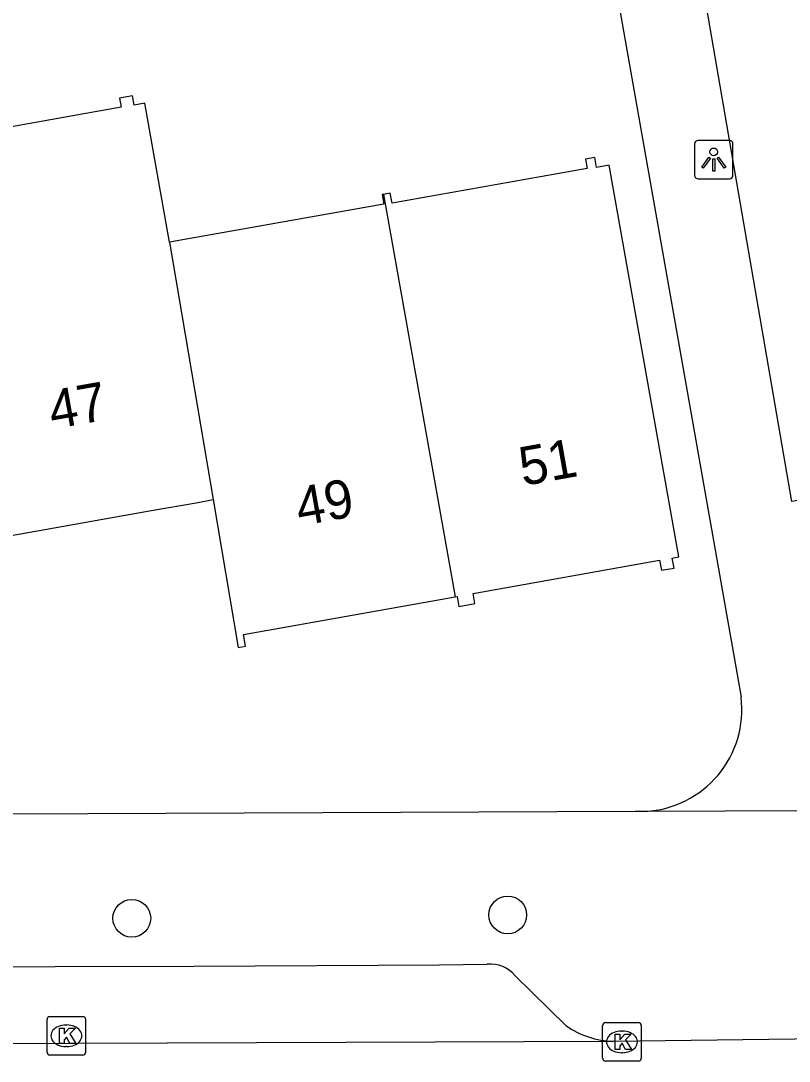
# Model space of a CAD drawing. Extents: x 157793 to 159380, y 380882 to 382313.
# Drawn here: x 158432.1 to 158452.01, y 381265.26 to 381292.23 of the extents above; entities that cross this region are included whole.
import ezdxf

# ---------------------------------------------------------------- set-up
doc = ezdxf.new("R2010")
doc.units = 0
for name, color, linetype in [('IMGEO_Boom', 7, 'Continuous'), ('IMGEO_Kolk', 7, 'Continuous'), ('IMGEO_Lichtpunt', 7, 'Continuous'), ('IMGEO_Pand', 7, 'Continuous'), ('IMGEO_Pand_nummerreeks', 7, 'Continuous'), ('IMGEO_Rijbaan_lokaal_gesloten', 7, 'Continuous'), ('IMGEO_Voetpad_open', 7, 'Continuous')]:
    doc.layers.add(name, color=color, linetype=linetype)

msp = doc.modelspace()

# ---------------------------------------------------------------- linework, layer by layer
at = {"layer": 'IMGEO_Boom'}
for centre in [(158434.973, 381268.967), (158444.714, 381269.054)]:
    msp.add_circle(centre, 0.489, dxfattribs=at)
at = {"layer": 'IMGEO_Kolk'}
for p, q in [((158432.851, 381266.422), (158433.703, 381266.422)), ((158432.776, 381265.496), (158432.776, 381266.348)), ((158433.264, 381266.202), (158433.289, 381266.202)), ((158433.777, 381266.348), (158433.777, 381265.496)), ((158447.175, 381265.338), (158447.175, 381266.19)), ((158447.25, 381266.264), (158448.102, 381266.264)), ((158448.176, 381266.19), (158448.176, 381265.338)), ((158447.663, 381266.044), (158447.688, 381266.044)), ((158433.287, 381265.642), (158433.262, 381265.642)), ((158433.703, 381265.422), (158432.851, 381265.422)), ((158447.686, 381265.484), (158447.661, 381265.484)), ((158448.102, 381265.264), (158447.25, 381265.264))]:
    msp.add_line(p, q, dxfattribs=at)
for points in [[(158432.851, 381266.422), (158433.703, 381266.422)], [(158432.776, 381265.496), (158432.776, 381266.348)], [(158433.097, 381266.122), (158433.22, 381266.122), (158433.22, 381265.971), (158433.35, 381266.122), (158433.514, 381266.122), (158433.368, 381265.971), (158433.521, 381265.722), (158433.369, 381265.722), (158433.284, 381265.886), (158433.22, 381265.819), (158433.22, 381265.722), (158433.097, 381265.722), (158433.097, 381266.122)], [(158433.777, 381266.348), (158433.777, 381265.496)], [(158447.175, 381265.338), (158447.175, 381266.19)], [(158447.25, 381266.264), (158448.102, 381266.264)], [(158448.176, 381266.19), (158448.176, 381265.338)], [(158447.496, 381265.964), (158447.619, 381265.964), (158447.619, 381265.813), (158447.749, 381265.964), (158447.913, 381265.964), (158447.767, 381265.813), (158447.92, 381265.564), (158447.768, 381265.564), (158447.683, 381265.728), (158447.619, 381265.661), (158447.619, 381265.564), (158447.496, 381265.564), (158447.496, 381265.964)], [(158433.703, 381265.422), (158432.851, 381265.422)], [(158448.102, 381265.264), (158447.25, 381265.264)]]:
    msp.add_lwpolyline(points, dxfattribs=at)
for centre, start, end in [((158432.853, 381266.346), 91.552, 178.448), ((158432.853, 381266.346), 91.552, 178.448), ((158433.701, 381266.346), 1.552, 88.448), ((158433.701, 381266.346), 1.552, 88.448), ((158447.252, 381266.188), 91.552, 178.448), ((158447.252, 381266.188), 91.552, 178.448), ((158448.1, 381266.188), 1.552, 88.448), ((158448.1, 381266.188), 1.552, 88.448), ((158432.853, 381265.498), 181.552, 268.448), ((158432.853, 381265.498), 181.552, 268.448), ((158433.701, 381265.498), 271.552, 358.448), ((158433.701, 381265.498), 271.552, 358.448), ((158447.252, 381265.34), 181.552, 268.448), ((158447.252, 381265.34), 181.552, 268.448), ((158448.1, 381265.34), 271.552, 358.448), ((158448.1, 381265.34), 271.552, 358.448)]:
    msp.add_arc(centre, 0.0765, start, end, dxfattribs=at)
for centre, major_axis, ratio, start_param, end_param in [((158433.263, 381265.922), (-0.387, 0.002), 0.722429, 4.712389, 7.853982), ((158433.288, 381265.922), (-0.39, 0.002), 0.717154, 1.570796, 4.712389), ((158447.662, 381265.764), (-0.387, 0.002), 0.722429, 4.712389, 7.853982), ((158447.687, 381265.764), (-0.39, 0.002), 0.717154, 1.570796, 4.712389)]:
    msp.add_ellipse(centre, major_axis=major_axis, ratio=ratio, start_param=start_param, end_param=end_param, dxfattribs=at)
at = {"layer": 'IMGEO_Lichtpunt'}
for p, q in [((158449.556, 381289.037), (158449.556, 381288.23)), ((158449.556, 381289.037), (158449.556, 381288.23)), ((158450.458, 381289.132), (158449.65, 381289.132)), ((158450.458, 381289.132), (158449.65, 381289.132)), ((158450.552, 381288.23), (158450.552, 381289.037)), ((158450.552, 381288.23), (158450.552, 381289.037)), ((158449.65, 381288.136), (158450.458, 381288.136)), ((158449.65, 381288.136), (158450.458, 381288.136))]:
    msp.add_line(p, q, dxfattribs=at)
for points in [[(158449.93, 381288.701), (158449.969, 381288.673), (158449.781, 381288.411), (158449.743, 381288.438), (158449.93, 381288.701)], [(158450.032, 381288.653), (158450.079, 381288.653), (158450.079, 381288.331), (158450.032, 381288.331), (158450.032, 381288.653)], [(158450.142, 381288.673), (158450.18, 381288.7), (158450.367, 381288.438), (158450.328, 381288.41), (158450.142, 381288.673)]]:
    msp.add_lwpolyline(points, dxfattribs=at)
msp.add_circle((158450.055, 381288.835), 0.0994, dxfattribs=at)
for centre, start, end in [((158449.65, 381289.037), 90, 180), ((158449.65, 381289.037), 90, 180), ((158450.458, 381289.037), 0, 90), ((158450.458, 381289.037), 0, 90), ((158449.65, 381288.23), 180, 270), ((158449.65, 381288.23), 180, 270), ((158450.458, 381288.23), 270, 0), ((158450.458, 381288.23), 270, 360)]:
    msp.add_arc(centre, 0.0946, start, end, dxfattribs=at)
at = {"layer": 'IMGEO_Pand'}
for points in [[(158435.954, 381286.49), (158435.311, 381290.099), (158435.03, 381290.049), (158434.987, 381290.287), (158434.655, 381290.228), (158434.698, 381289.99), (158429.536, 381289.071)], [(158443.354, 381277.3), (158443.401, 381277.308), (158443.447, 381277.051), (158443.864, 381277.125), (158443.817, 381277.389), (158448.65, 381278.25), (158448.696, 381277.988), (158449.024, 381278.046), (158448.977, 381278.305), (158449.151, 381278.336), (158447.341, 381288.491), (158447.014, 381288.433), (158446.969, 381288.685), (158446.73, 381288.642), (158446.773, 381288.404), (158441.716, 381287.503), (158441.67, 381287.764), (158441.494, 381287.733)], [(158441.494, 381287.733), (158441.46, 381287.727), (158441.504, 381287.479), (158435.954, 381286.49)], [(158441.494, 381287.733), (158443.354, 381277.3)], [(158435.954, 381286.49), (158437.08, 381279.82)], [(158431.357, 381278.8), (158435.523, 381279.543), (158436.637, 381279.741), (158437.08, 381279.82)], [(158437.08, 381279.82), (158437.727, 381275.987), (158437.92, 381276.021), (158437.867, 381276.322), (158443.354, 381277.3)]]:
    msp.add_lwpolyline(points, dxfattribs=at)
at = {"layer": 'IMGEO_Rijbaan_lokaal_gesloten'}
for points in [[(158447.459, 381265.784), (158453.494, 381265.863)], [(158394.254, 381265.587), (158447.459, 381265.784)]]:
    msp.add_lwpolyline(points, dxfattribs=at)
at = {"layer": 'IMGEO_Voetpad_open'}
for points in [[(158445.405, 381305.032), (158450.762, 381274.698)], [(158455.873, 381280.446), (158452.075, 381279.774), (158447.84, 381304.388), (158451.622, 381305.07)], [(158458.608, 381271.782), (158448.288, 381271.738)], [(158448.288, 381271.738), (158448.019, 381271.737), (158393.303, 381271.505)], [(158397.113, 381267.591), (158398.123, 381267.602), (158404.457, 381267.623), (158408.624, 381267.65), (158422.206, 381267.693), (158426.333, 381267.709), (158432.987, 381267.722), (158436.58, 381267.729), (158442.946, 381267.765), (158444.184, 381267.778)], [(158444.91, 381267.475), (158446.219, 381266.19)]]:
    msp.add_lwpolyline(points, dxfattribs=at)
for centre, radius, start, end in [((158448.142, 381274.374), 2.64, 273.1635, 7.058), ((158444.258, 381266.934), 0.847, 39.6831, 95.01), ((158447.486, 381267.963), 2.18, 234.4533, 269.2878)]:
    msp.add_arc(centre, radius, start, end, dxfattribs=at)

# ---------------------------------------------------------------- texts
at = {"layer": 'IMGEO_Pand_nummerreeks'}
for s, rotation, p in [('47', 10.0325, (158432.914, 381281.642)), ('51', 10.1299, (158445.107, 381280.173)), ('49', 10.2158, (158439.318, 381279.132))]:
    msp.add_text(s, height=1, rotation=rotation, dxfattribs=at).set_placement(p)

doc.saveas('drawing.dxf')
